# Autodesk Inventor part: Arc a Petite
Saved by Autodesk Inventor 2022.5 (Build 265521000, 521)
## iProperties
Created: 2024-07
Part Number: Arc a Petite
Material: Generic
Document SubType Name: Modeling
Designer: AdminForWorker
Density: 1 g/cm^3
Appearance: Default
Title: Arc a Petite
Author: AdminForWorker
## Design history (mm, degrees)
feature "Arca Petite"
body "Solid1"
